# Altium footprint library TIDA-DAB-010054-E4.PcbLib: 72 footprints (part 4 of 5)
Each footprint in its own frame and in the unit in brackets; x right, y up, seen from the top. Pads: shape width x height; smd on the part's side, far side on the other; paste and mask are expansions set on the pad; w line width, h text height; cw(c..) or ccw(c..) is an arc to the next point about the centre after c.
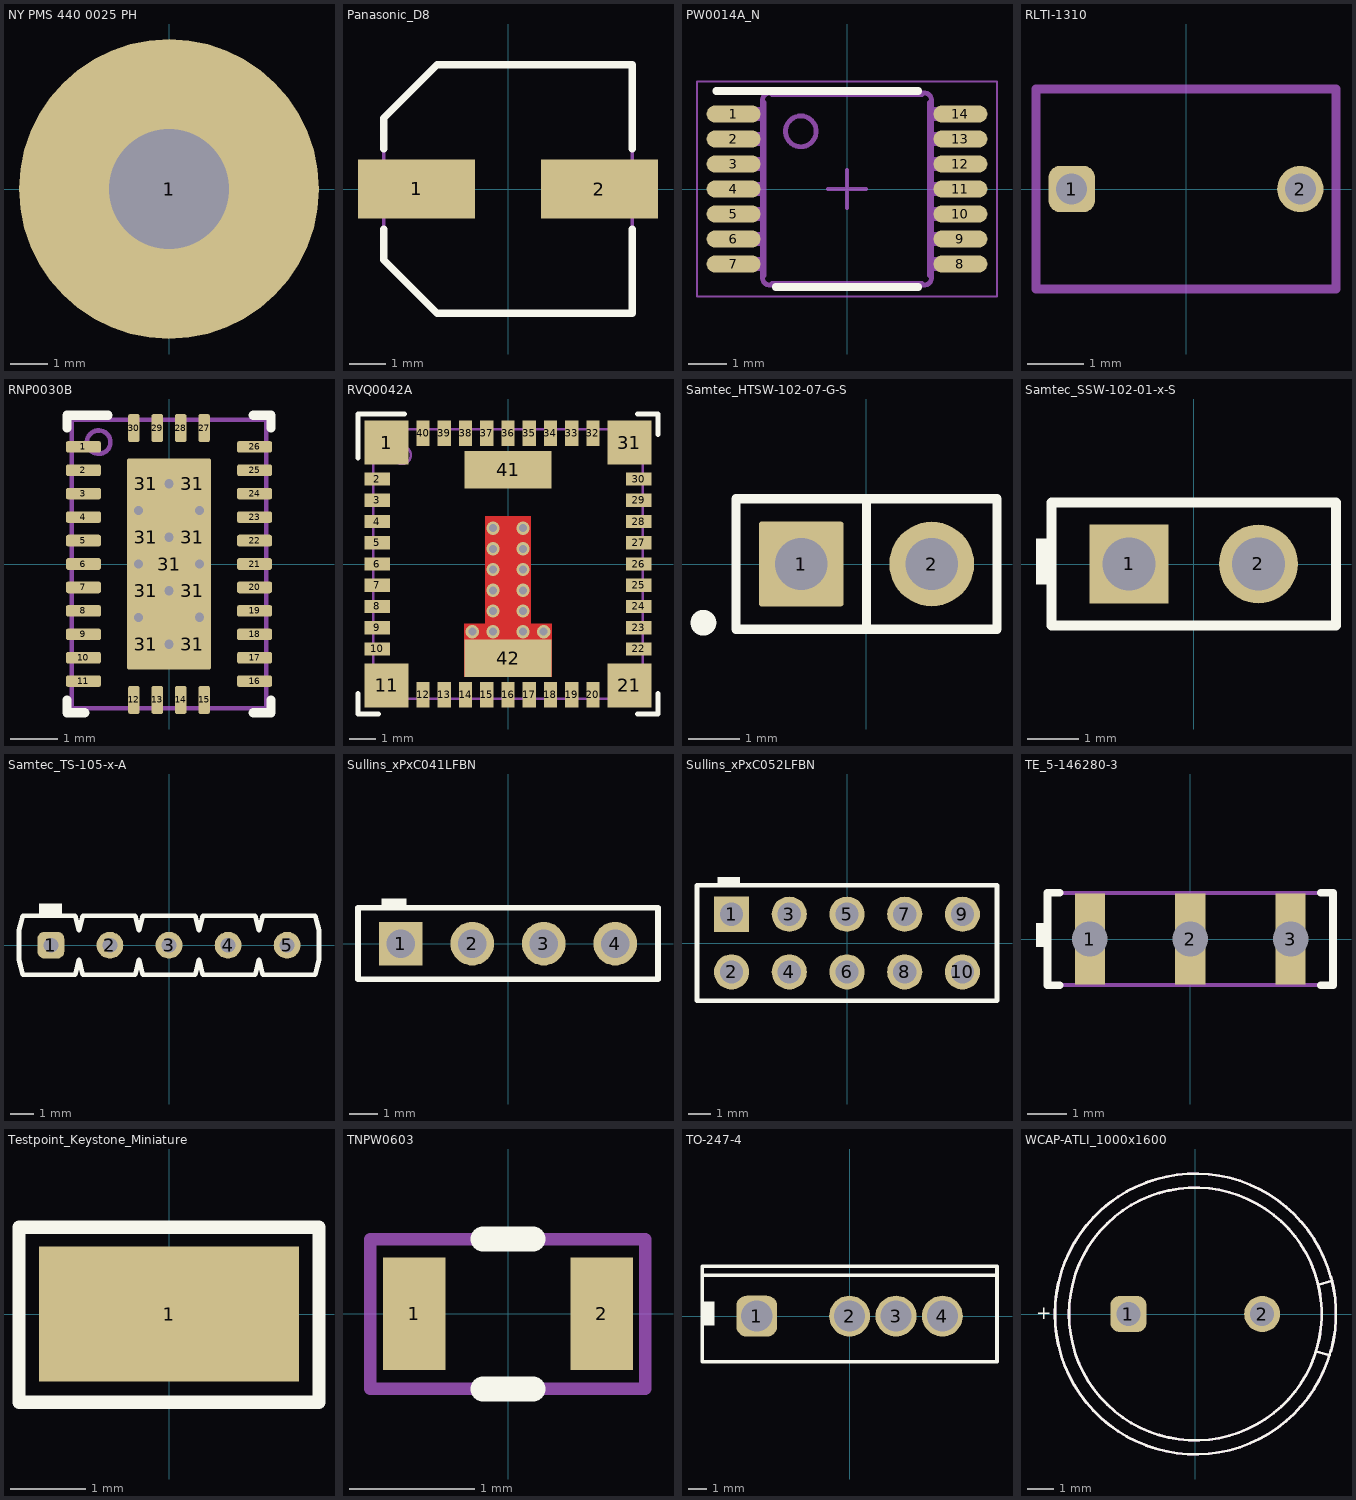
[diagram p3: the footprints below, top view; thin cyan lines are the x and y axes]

## NY PMS 440 0025 PH [mm] "4-40 nylon screw and mounting hole"
height 1.905
pads (1):
  round 8 hole 3.2: 1(0,0)
Mechanical 5:
  circle w0.127: c0,0 r3.789
  text ".Designator" at -0.229,-0.428 h0.51
3D body "B_F_NY PMS 440 0025 PH.stp": height 2.69, standoff -8.74, extent -3.302,-3.3 3.296,3.3

## Panasonic_D8 [mm] "SMD, 2-Leads, Dia 6.3mm"
height 8
pads (2):
  rect 3.2x1.6 smd: 1(-2.5,0) 2(2.5,0)
Top Overlay:
  lines w0.2: -3.4,-1.099 -3.4,-1.942 -1.94,-3.4 3.4,-3.4 3.4,-1.1 ; -3.4,1.099 -3.4,1.942 -1.94,3.4 3.4,3.4 3.4,1.1
Mechanical 5:
  lines w0.1: -3.4,-1.942 -3.4,1.942 ; -3.398,-1.942 -1.94,-3.4 3.4,-3.4 3.4,3.4 -1.94,3.4 -3.398,1.942
  text ".Designator" at -0.305,0.762 h0.51
3D body: height 0.6, standoff 0, extent -3.398,-3.401 3.401,3.401
3D body: height 8.01, standoff 7.9, extent 1.097,-3.015 3.208,3.015
3D body: height 8, standoff 0.6, extent -3.399,-3.399 3.399,3.399

## PW0014A_N [mm] "TSOP, 14-Leads, Body 5x4.4mm, Pitch 0.65mm, IPC Medium Density"
height 1.2
pads (14):
  oval 1.4x0.45 smd: 1(-2.95,1.95) 2(-2.95,1.3) 3(-2.95,0.65) 4(-2.95,0) 5(-2.95,-0.65) 6(-2.95,-1.3) 7(-2.95,-1.95) 8(2.95,-1.95) 9(2.95,-1.3) 10(2.95,-0.65) 11(2.95,0) 12(2.95,0.65) 13(2.95,1.3) 14(2.95,1.95)
Top Overlay:
  lines w0.2: -3.4,2.55 1.85,2.55 ; -1.85,-2.55 1.85,-2.55
Mechanical 5:
  drawing of 182 lines, arcs and shapes, not listed
  text ".Designator" at 0.41,0.193 h0.51
Mechanical 15:
  lines w0.05: -3.9,-2.8 -3.9,2.8 3.9,2.8 3.9,-2.8 -3.9,-2.8
  lines w0.1: -0.5,0 0.5,0 ; 0,-0.5 0,0.5
3D body "PW0014A.stp": height 1, standoff 0, extent -3.21,-2.5 3.21,2.5

## RLTI-1310 [mm] "TH, Dia 735mil"
height 18.669
pads (2):
  rrect50% 0.825x0.825 hole 0.55: 1(-2.032,0)
  round 0.825 hole 0.55: 2(2.032,0)
Mechanical 5:
  lines w0.152: -2.667,-1.778 2.667,-1.778 2.667,0 2.667,1.778 -2.667,1.778 -2.667,0 -2.667,-1.778
  text ".Designator" at 0.215,0.325 h0.51

## RNP0030B [mm] "QFN, 30-Leads, Body 6x4mm, Pitch 0.5mm, Thermal Pad 1.8x4.5mm"
height 0.8
pads (39):
  rrect40% 0.75x0.25 smd: 1(-1.825,2.5) 2(-1.825,2) 3(-1.825,1.5) 4(-1.825,1) 5(-1.825,0.5) 6(-1.825,0) 7(-1.825,-0.5) 8(-1.825,-1) 9(-1.825,-1.5) 10(-1.825,-2) 11(-1.825,-2.5) 16(1.825,-2.5) 17(1.825,-2) 18(1.825,-1.5) 19(1.825,-1) 20(1.825,-0.5) 21(1.825,0) 22(1.825,0.5) 23(1.825,1) 24(1.825,1.5) 25(1.825,2) 26(1.825,2.5)
  rrect40% 0.25x0.6 smd: 12(-0.75,-2.9) 13(-0.25,-2.9) 14(0.25,-2.9) 15(0.75,-2.9) 27(0.75,2.9) 28(0.25,2.9) 29(-0.25,2.9) 30(-0.75,2.9)
  rrect50% 0.8x0.94 on Top Paste: 31(-0.5,0.57) 31(-0.5,1.71) 31(-0.5,-1.71) 31(-0.5,-0.57) 31(0.5,0.57) 31(0.5,1.71) 31(0.5,-1.71) 31(0.5,-0.57)
  rrect5% 1.8x4.5 smd paste-3: 31(0,0)
via 0.65,-1.14 diameter 0.5 hole 0.2
via -0.65,-1.14 diameter 0.5 hole 0.2
via 0,-1.71 diameter 0.5 hole 0.2
via 0,-0.57 diameter 0.5 hole 0.2
via 0,0.57 diameter 0.5 hole 0.2
via 0,1.71 diameter 0.5 hole 0.2
via -0.65,1.14 diameter 0.5 hole 0.2
via 0.65,1.14 diameter 0.5 hole 0.2
via 0.65,0 diameter 0.5 hole 0.2
via -0.65,0 diameter 0.5 hole 0.2
Top Overlay:
  lines w0.2: -2.175,-2.9 -2.175,-3.175 -1.8,-3.175 ; -2.175,2.9 -2.175,3.175 -1.3,3.175 ; 1.8,-3.175 2.175,-3.175 2.175,-2.9 ; 1.8,3.175 2.175,3.175 2.175,2.9
Mechanical 5:
  circle w0.1: c-1.5,2.6 r0.25
  lines w0.1: -2.075,-3.075 2.075,-3.075 2.075,3.075 -2.075,3.075 -2.075,-3.075
  text ".Designator" at 0.25,-0.475 h0.51
3D body "RNP0030B.stp": height 0.8, standoff 0, extent -2,-3 2,3

## RVQ0042A [mm]
height 4.4
pads (42):
  rect 1.65x1.65 smd paste-0.225: 1(-4.575,4.575) 11(-4.575,-4.575) 21(4.575,-4.575) 31(4.575,4.575)
  rect 0.95x0.5 smd paste-0.025: 2(-4.925,3.2) 3(-4.925,2.4) 4(-4.925,1.6) 5(-4.925,0.8) 6(-4.925,0) 7(-4.925,-0.8) 8(-4.925,-1.6) 9(-4.925,-2.4) 10(-4.925,-3.2) 22(4.925,-3.2) 23(4.925,-2.4) 24(4.925,-1.6) 25(4.925,-0.8) 26(4.925,0) 27(4.925,0.8) 28(4.925,1.6) 29(4.925,2.4) 30(4.925,3.2)
  rect 0.5x0.95 smd paste-0.025: 12(-3.2,-4.925) 13(-2.4,-4.925) 14(-1.6,-4.925) 15(-0.8,-4.925) 16(0,-4.925) 17(0.8,-4.925) 18(1.6,-4.925) 19(2.4,-4.925) 20(3.2,-4.925) 32(3.2,4.925) 33(2.4,4.925) 34(1.6,4.925) 35(0.8,4.925) 36(0,4.925) 37(-0.8,4.925) 38(-1.6,4.925) 39(-2.4,4.925) 40(-3.2,4.925)
  rect 3.29x1.4 smd paste-1: 41(0,3.55)
  rect 3.29x1.4 smd paste-1 mask+0: 42(0,-3.55)
via 1.342,-2.55 diameter 0.5 hole 0.3
via 0.562,-2.55 diameter 0.5 hole 0.3
via 0.562,-1.77 diameter 0.5 hole 0.3
via 0.563,-0.99 diameter 0.5 hole 0.3
via 0.562,-0.21 diameter 0.5 hole 0.3
via 0.563,0.57 diameter 0.5 hole 0.3
via 0.562,1.35 diameter 0.5 hole 0.3
via -0.563,1.35 diameter 0.5 hole 0.3
via -0.563,0.57 diameter 0.5 hole 0.3
via -0.563,-0.21 diameter 0.5 hole 0.3
via -0.563,-0.99 diameter 0.5 hole 0.3
via -0.563,-1.77 diameter 0.5 hole 0.3
via -0.563,-2.55 diameter 0.5 hole 0.3
via -1.343,-2.55 diameter 0.5 hole 0.3
Top Layer:
  region: -1.645,-4.25 -1.645,-2.25 -0.863,-2.25 -0.863,1.8 0.863,1.8 0.863,-2.25 1.645,-2.25 1.645,-4.25
Top Overlay:
  lines w0.2: -5.65,-4.875 -5.65,-5.65 -4.875,-5.65 ; 4.875,-5.65 5.65,-5.65 5.65,-4.875 ; 4.875,5.65 5.65,5.65 5.65,4.875
  lines w0.203: -5.65,4 -5.65,5.65 -3.9,5.65
Top Paste:
  region: 0.15,-3.4 1.62,-3.4 1.62,-2.87 0.15,-2.87
  region: 0.15,-4.23 1.62,-4.23 1.62,-3.7 0.15,-3.7
  region: -1.62,-4.23 -0.15,-4.23 -0.15,-3.7 -1.62,-3.7
  region: -1.62,-3.4 -0.15,-3.4 -0.15,-2.87 -1.62,-2.87
  region: -0.238,-2.518 0.238,-2.518 0.238,-1.288 -0.238,-1.288
  region: -0.238,-0.988 0.238,-0.988 0.238,0.242 -0.238,0.242
  region: -0.238,0.543 0.238,0.542 0.237,1.772 -0.238,1.773
  region: 0.15,3.7 1.62,3.7 1.62,4.23 0.15,4.23
  region: 0.15,2.87 1.62,2.87 1.62,3.4 0.15,3.4
  region: -1.62,2.87 -0.15,2.87 -0.15,3.4 -1.62,3.4
  region: -1.62,3.7 -0.15,3.7 -0.15,4.23 -1.62,4.23
Top Solder:
  region: 1.645,-4.25 -1.645,-4.25 -1.645,-2.85 -0.262,-2.85 -0.262,1.8 0.263,1.8 0.263,-2.85 1.645,-2.85
Mechanical 5:
  circle w0.1: c-3.989,4.1 r0.329
  lines w0.1: -5.075,-5.075 5.075,-5.075 5.075,5.075 -5.075,5.075 -5.075,-5.075
  text ".Designator" at -0.356,-0.435 h0.51
3D body: height 4.4, standoff 0, extent -5.074,-5.074 5.074,5.074
3D body: height 4.41, standoff 2, extent -4.317,3.772 -3.661,4.428

## Samtec_HTSW-102-07-G-S [mm] "Samtec 100mil, 1x2, 230 mil above insulator"
height 8.382
pads (2):
  rrect6% 1.65x1.65 hole 1.016: 1(-1.27,0)
  round 1.65 hole 1.016: 2(1.27,0)
Top Overlay:
  circle w0.25: c-3.173,-1.143 r0.125
  lines w0.178: 0,-1.27 0,1.27 ; -2.54,-1.27 2.54,-1.27 2.54,1.27 -2.54,1.27 -2.54,-1.27
Mechanical 5:
  lines w0.127: -2.54,-1.27 -2.54,1.27 2.54,1.27 2.54,-1.27 -2.54,-1.27
  text ".Designator" at 0.951,0.396 h0.51
3D body: height 2.54, standoff 0, extent -2.539,-1.269 2.539,1.269
3D body: height 8.38, standoff -2.03, extent -1.587,-0.317 -0.953,0.317
3D body: height 8.38, standoff -2.03, extent 0.953,-0.317 1.587,0.317

## Samtec_SSW-102-01-x-S [mm] "Receptacle, 2x1, 2.54mm, TH"
height 8.64
pads (2):
  rect 1.55x1.55 hole 1.04: 1(-1.27,0)
  round 1.55 hole 1.04: 2(1.27,0)
Top Overlay:
  rectangle: -3.1,-0.4 -2.8,0.5
  lines w0.2: -2.794,-1.206 -2.794,1.207 2.794,1.207 2.794,-1.206 -2.794,-1.206
Mechanical 5:
  lines w0.1: -2.794,-1.206 2.794,-1.206 2.794,1.207 -2.794,1.207 -2.794,-1.206
  text ".Designator" at 0.371,-0.663 h0.51
3D body "SSW-102-01-T-S.stp": height 8.51, standoff -2.64, extent -2.788,-1.213 2.8,1.2

## Samtec_TS-105-x-A [mm] "Header, 2.54mm, 5x1, TH"
height 8.08
pads (5):
  rrect50% 1.15x1.15 hole 0.635: 1(-5.08,0)
  round 1.15 hole 0.635: 2(-2.54,0) 3(0,0) 4(2.54,0) 5(5.08,0)
Top Overlay:
  rectangle: -5.6,1.32 -4.6,1.8
  lines w0.2: -6.452,-0.635 -6.452,0.635 -6.281,1.27 -4.041,1.27 -3.871,0.635 -3.701,1.27 -1.46,1.27 -1.29,0.635 -1.12,1.27 1.12,1.27 1.29,0.635 1.46,1.27 3.701,1.27 3.871,0.635 4.041,1.27 6.281,1.27 6.452,0.635 6.452,-0.635 6.281,-1.27 4.041,-1.27 3.871,-0.635 3.701,-1.27 1.46,-1.27 1.29,-0.635 1.12,-1.27 -1.12,-1.27 -1.29,-0.635 -1.46,-1.27 -3.701,-1.27 -3.871,-0.635 -4.041,-1.27 -6.281,-1.27 -6.452,-0.635
Mechanical 5:
  lines w0.1: -6.452,-0.635 -6.452,0.635 -6.281,1.27 -4.041,1.27 -3.871,0.635 -3.701,1.27 -1.46,1.27 -1.29,0.635 -1.12,1.27 1.12,1.27 1.29,0.635 1.46,1.27 3.701,1.27 3.871,0.635 4.041,1.27 6.281,1.27 6.452,0.635 6.452,-0.635 6.281,-1.27 4.041,-1.27 3.871,-0.635 3.701,-1.27 1.46,-1.27 1.29,-0.635 1.12,-1.27 -1.12,-1.27 -1.29,-0.635 -1.46,-1.27 -3.701,-1.27 -3.871,-0.635 -4.041,-1.27 -6.281,-1.27 -6.452,-0.635
  text ".Designator" at -0.203,-0.483 h0.51
3D body "TS-105-G-A.stp": height 8.28, standoff -3.84, extent -6.452,-1.27 6.452,1.27

## Sullins_xPxC041LFBN [mm] "Receptacle, 2.54mm, 4x1, TH"
height 8.65
pads (4):
  rect 1.55x1.55 hole 1.02: 1(-3.81,0)
  round 1.55 hole 1.02: 2(-1.27,0) 3(1.27,0) 4(3.81,0)
Top Overlay:
  rectangle: -4.5,1.345 -3.6,1.6
  lines w0.2: -5.33,-1.27 5.33,-1.27 5.33,1.27 -5.33,1.27 -5.33,-1.27
Mechanical 5:
  lines w0.1: -5.33,-1.27 -5.33,1.27 5.33,1.27 5.33,-1.27 -5.33,-1.27
  text ".Designator" at 0.216,-0.659 h0.51
3D body "PPTC041LFBN-RC.stp": height 8.5, standoff -3.2, extent -5.33,-1.27 5.33,1.27

## Sullins_xPxC052LFBN [mm] "Receptacle, 2.54mm, 5x2, TH"
height 8.65
pads (10):
  rect 1.55x1.55 hole 1.02: 1(-5.08,1.27)
  round 1.55 hole 1.02: 2(-5.08,-1.27) 3(-2.54,1.27) 4(-2.54,-1.27) 5(0,1.27) 6(0,-1.27) 7(2.54,1.27) 8(2.54,-1.27) 9(5.08,1.27) 10(5.08,-1.27)
Top Overlay:
  rectangle: -5.7,2.54 -4.7,2.9
  lines w0.2: -6.6,-2.54 -6.6,2.54 6.6,2.54 6.6,-2.54 -6.6,-2.54
Mechanical 5:
  lines w0.1: -6.6,-2.54 6.6,-2.54 6.6,2.54 -6.6,2.54 -6.6,-2.54
  text ".Designator" at 0.273,-0.781 h0.51
3D body "xPxC052LFBN-RC.stp": height 8.5, standoff -3.2, extent -6.6,-2.54 6.6,2.54

## TE_5-146280-3 [mm] "Header, 2.54mm, 3x1, TH"
height 8.72
pads (3):
  rect 0.76x2.29 hole 0.89: 1(-2.54,0) 2(0,0) 3(2.54,0)
Top Overlay:
  rectangle: -3.9,-0.2 -3.6,0.4
  lines w0.2: -3.3,-1.168 -3.607,-1.168 -3.607,1.169 -3.3,1.169 ; 3.3,-1.168 3.607,-1.168 3.607,1.169 3.3,1.169
Mechanical 5:
  lines w0.1: -3.607,-1.168 -3.607,1.169 3.607,1.169 3.607,-1.168 -3.607,-1.168 ; -2.851,-0.311 -2.851,0.311 -2.229,0.311 -2.229,-0.311 -2.851,-0.311
  text ".Designator" at 0.356,0.311 h0.51
3D body "c-5-146280-3-g-3d.stp": height 8.13, standoff -3.05, extent -3.607,-1.168 3.607,1.169

## Testpoint_Keystone_Miniature [mil] "Miniature SMT test point"
height 90.55
pads (1):
  rect 135x70 smd: 1(0,0)
Top Overlay:
  lines w7: -78,-46 -78,-38 -78,45 -65,45 5,45 78,45 78,-46 -78,-46
Mechanical 5:
  lines w5: -78,-46 78,-46 78,45 5,45 -65,45 -78,45 -78,-38 -78,-46
  text ".Designator" at -22,-14 h20
3D body "keystone_5015.stp": height 60.6, standoff 0.6, extent -52.5,-20 52.5,20

## TNPW0603 [mm] "Vishay"
height 0.55
pads (2):
  rect 0.5x0.9 smd: 1(-0.75,0) 2(0.75,0)
Top Overlay:
  lines w0.2: -0.2,-0.6 0.2,-0.6 ; -0.2,0.6 0.2,0.6
Mechanical 5:
  lines w0.1: -1.1,-0.6 1.1,-0.6 1.1,0.6 -1.1,0.6 -1.1,-0.6
  text ".Designator" at -0.596,-0.196 h0.51
3D body: height 0.55, standoff 0, extent 0.501,-0.474 0.849,0.474
3D body: height 0.55, standoff 0, extent -0.499,-0.474 0.499,0.474
3D body: height 0.55, standoff 0, extent -0.849,-0.474 -0.501,0.474

## TO-247-4 [mm] "FM, 4-Leads, Body 15.94x5.02mm, Pitch 2.54mm"
height 27.97
pads (4):
  rrect50% 2.24x2.24 hole 1.7: 1(-5.08,0)
  round 2.24 hole 1.7: 2(0,0) 3(2.54,0) 4(5.08,0)
Top Overlay:
  region: -7.4,-0.5 -7.4,0.8 -8,0.8 -8,-0.5
  lines w0.2: -8.065,2.245 8.065,2.245 ; -8.065,-2.488 -8.065,2.722 8.065,2.722 8.065,-2.488 -8.065,-2.488
Mechanical 5:
  lines w0.1: -8.065,2.245 8.065,2.245 ; -8.065,-2.488 8.065,-2.488 8.065,2.722 -8.065,2.722 -8.065,-2.488
  text ".Designator" at 6.239,1.007 h0.51
3D body: height 27.97, standoff 3.97, extent -8.065,-2.488 8.065,2.722
3D body: height 3.97, standoff 0, extent -5.635,-0.31 -4.525,0.31
3D body: height 0, standoff -1.6, extent -5.68,-0.31 -4.48,0.31
3D body: height 3.97, standoff 0, extent -0.555,-0.31 0.555,0.31
3D body: height 0, standoff -1.6, extent -0.6,-0.31 0.6,0.31
3D body: height 3.97, standoff 0, extent 1.985,-0.31 3.095,0.31
3D body: height 0, standoff -1.6, extent 1.94,-0.31 3.14,0.31
3D body: height 3.97, standoff 0, extent 4.525,-0.31 5.635,0.31
3D body: height 0, standoff -1.6, extent 4.48,-0.31 5.68,0.31
3D body: height 27.97, standoff 20.02, extent -6.825,2.72 6.825,2.72
3D body: height 20.06, standoff 20.02, extent -6.825,2.72 -0.351,2.72
3D body: height 20.06, standoff 20.02, extent 0.351,2.72 6.825,2.72
3D body: height 23.62, standoff 23.59, extent -6.825,2.72 -0.351,2.72
3D body: height 23.62, standoff 23.59, extent 0.351,2.72 6.825,2.72
3D body: height 20.16, standoff 20.05, extent -6.825,2.72 -0.689,2.72
3D body: height 20.16, standoff 20.05, extent 0.689,2.72 6.825,2.72
3D body: height 23.59, standoff 23.48, extent -6.825,2.72 -0.689,2.72
3D body: height 23.59, standoff 23.48, extent 0.689,2.72 6.825,2.72
3D body: height 20.33, standoff 20.16, extent -6.825,2.72 -1,2.72
3D body: height 20.33, standoff 20.16, extent 1,2.72 6.825,2.72
3D body: height 23.49, standoff 23.32, extent -6.825,2.72 -1,2.72
3D body: height 23.49, standoff 23.32, extent 1,2.72 6.825,2.72
3D body: height 20.55, standoff 20.32, extent -6.825,2.72 -1.273,2.72
3D body: height 20.55, standoff 20.32, extent 1.273,2.72 6.825,2.72
3D body: height 23.32, standoff 23.09, extent -6.825,2.72 -1.273,2.72
3D body: height 23.32, standoff 23.09, extent 1.273,2.72 6.825,2.72
3D body: height 20.82, standoff 20.55, extent -6.825,2.72 -1.497,2.72
3D body: height 20.82, standoff 20.55, extent 1.497,2.72 6.825,2.72
3D body: height 23.1, standoff 22.82, extent -6.825,2.72 -1.497,2.72
3D body: height 23.1, standoff 22.82, extent 1.497,2.72 6.825,2.72
3D body: height 21.14, standoff 20.82, extent -6.825,2.72 -1.663,2.72
3D body: height 21.14, standoff 20.82, extent 1.663,2.72 6.825,2.72
3D body: height 22.83, standoff 22.51, extent -6.825,2.72 -1.663,2.72
3D body: height 22.83, standoff 22.51, extent 1.663,2.72 6.825,2.72
3D body: height 21.47, standoff 21.13, extent -6.825,2.72 -1.765,2.72
3D body: height 21.47, standoff 21.13, extent 1.765,2.72 6.825,2.72
3D body: height 22.51, standoff 22.17, extent -6.825,2.72 -1.765,2.72
3D body: height 22.51, standoff 22.17, extent 1.765,2.72 6.825,2.72
3D body: height 21.82, standoff 21.47, extent -6.825,2.72 -1.8,2.72
3D body: height 21.82, standoff 21.47, extent 1.8,2.72 6.825,2.72
3D body: height 22.18, standoff 21.82, extent -6.825,2.72 -1.8,2.72
3D body: height 22.18, standoff 21.82, extent 1.8,2.72 6.825,2.72
3D body: height 27.97, standoff 23.62, extent -6.825,2.72 6.825,2.72
3D body: height 27.97, standoff 23.62, extent -6.825,2.72 6.825,2.72
3D body: height 22.18, standoff 21.82, extent 1.8,2.72 6.825,2.72
3D body: height 22.18, standoff 21.82, extent -6.825,2.72 -1.8,2.72
3D body: height 21.82, standoff 21.47, extent 1.8,2.72 6.825,2.72
3D body: height 21.82, standoff 21.47, extent -6.825,2.72 -1.8,2.72
3D body: height 22.51, standoff 22.17, extent 1.765,2.72 6.825,2.72
3D body: height 22.51, standoff 22.17, extent -6.825,2.72 -1.765,2.72
3D body: height 21.47, standoff 21.13, extent 1.765,2.72 6.825,2.72
3D body: height 21.47, standoff 21.13, extent -6.825,2.72 -1.765,2.72
3D body: height 22.83, standoff 22.51, extent 1.663,2.72 6.825,2.72
3D body: height 22.83, standoff 22.51, extent -6.825,2.72 -1.663,2.72
3D body: height 21.14, standoff 20.82, extent 1.663,2.72 6.825,2.72
3D body: height 21.14, standoff 20.82, extent -6.825,2.72 -1.663,2.72
3D body: height 23.1, standoff 22.82, extent 1.497,2.72 6.825,2.72
3D body: height 23.1, standoff 22.82, extent -6.825,2.72 -1.497,2.72
3D body: height 20.82, standoff 20.55, extent 1.497,2.72 6.825,2.72
3D body: height 20.82, standoff 20.55, extent -6.825,2.72 -1.497,2.72
3D body: height 23.32, standoff 23.09, extent 1.273,2.72 6.825,2.72
3D body: height 23.32, standoff 23.09, extent -6.825,2.72 -1.273,2.72
3D body: height 20.55, standoff 20.32, extent 1.273,2.72 6.825,2.72
3D body: height 20.55, standoff 20.32, extent -6.825,2.72 -1.273,2.72
3D body: height 23.49, standoff 23.32, extent 1,2.72 6.825,2.72
3D body: height 23.49, standoff 23.32, extent -6.825,2.72 -1,2.72
3D body: height 20.33, standoff 20.16, extent 1,2.72 6.825,2.72
3D body: height 20.33, standoff 20.16, extent -6.825,2.72 -1,2.72
3D body: height 23.59, standoff 23.48, extent 0.689,2.72 6.825,2.72
3D body: height 23.59, standoff 23.48, extent -6.825,2.72 -0.689,2.72
3D body: height 20.16, standoff 20.05, extent 0.689,2.72 6.825,2.72
3D body: height 20.16, standoff 20.05, extent -6.825,2.72 -0.689,2.72
3D body: height 23.62, standoff 23.59, extent 0.351,2.72 6.825,2.72
3D body: height 23.62, standoff 23.59, extent -6.825,2.72 -0.351,2.72
3D body: height 20.06, standoff 20.02, extent 0.351,2.72 6.825,2.72
3D body: height 20.06, standoff 20.02, extent -6.825,2.72 -0.351,2.72
3D body: height 27.97, standoff 20.02, extent -6.825,2.72 6.825,2.72

## WCAP-ATLI_1000x1600 [mm] "TH, 2-Leads, Dia 10mm, Pin Spacing 5mm"
height 17.5
pads (2):
  rrect50% 1.35x1.35 hole 0.9: 1(-2.5,0)
  round 1.35 hole 0.9: 2(2.5,0)
Top Overlay:
  lines w0.1: 4.5,-1.4 5.017,-1.538 ; 4.6,1.1 5.117,1.238 ; 5.071,-1.359 cw(c0,0) 5.071,1.359 ; 5.081,-1.362 ccw(c0,0) 5.081,1.362 ; 4.564,-1.223 cw(c0,0) 4.564,1.223 cw(c0,0) 4.564,-1.223
  text "+" at -5.958,-0.203 h0.51
Mechanical 5:
  lines w0.1: 4.5,-1.4 5.017,-1.538 ; 4.6,1.1 5.117,1.238 ; 5.071,-1.359 cw(c0,0) 5.071,1.359 ; 5.081,-1.362 ccw(c0,0) 5.081,1.362 ; 4.564,-1.223 ccw(c0,0) 4.564,1.223 ccw(c0,0) 4.564,-1.223
  text ".Designator" at 0.849,0.4 h0.51
  text "+" at -5.958,-0.203 h0.51
3D body "860080675015.stp": height 17.51, standoff -4, extent -5.25,-5.248 5.26,5.248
